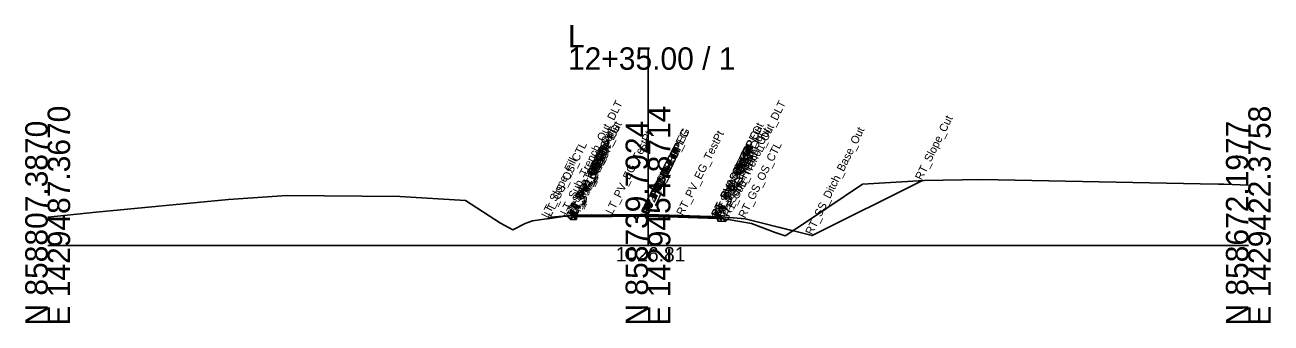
# Model space of a CAD drawing. Extents: x -26 to 2303, y -10 to 19558.
# Drawn here: x 1147.2 to 1302.8, y 990.3 to 1027.6 of the extents above; entities that cross this region are included whole.
import ezdxf

# ---------------------------------------------------------------- set-up
doc = ezdxf.new("R2010")
doc.units = 0
for name, color, linetype in [('Default', 7, 'Continuous'), ('Exist CMT Pavement', 7, 'Continuous'), ('Exist Cross Section Cell', 7, 'Continuous'), ('Exist XS Center Line Elevation Label', 7, 'Continuous'), ('Exist XS Ground Line', 7, 'Continuous'), ('Old_Level_50', 7, 'Continuous'), ('Prop CMT Pvmt Course 1', 7, 'Continuous'), ('Prop CMT Pvmt Course 1 Wedge', 7, 'Continuous'), ('Prop CMT Pvmt Course 2', 7, 'Continuous'), ('Prop CMT Pvmt Course 2 Wedge', 7, 'Continuous'), ('Prop CMT Pvmt Surface', 7, 'Continuous'), ('Prop CMT Pvmt Surface Shoulder', 7, 'Continuous'), ('Prop CMT Pvmt Wedge Surface 1', 7, 'Continuous'), ('Prop CMT Pvmt Wedge Surface 2', 7, 'Continuous'), ('Prop CMT Shld Paved Course 1', 7, 'Continuous'), ('Prop CMT Shld Paved Course 2', 7, 'Continuous'), ('Prop CMT Slope Grass', 7, 'Continuous'), ('Prop CMT Subgrade Earthwork', 7, 'Continuous'), ('Prop XS Dump Level', 7, 'Continuous')]:
    doc.layers.add(name, color=color, linetype=linetype)

msp = doc.modelspace()

# ---------------------------------------------------------------- linework, layer by layer
at = {"layer": 'Exist CMT Pavement'}
for points in [[(1225, 1003.81), (1216.08, 1003.82)], [(1216.08, 1003.82), (1220.54, 1003.82)], [(1220.54, 1003.82), (1225, 1003.81)], [(1229.37, 1003.65), (1225, 1003.81)], [(1225, 1003.81), (1233.74, 1003.47)], [(1233.74, 1003.47), (1229.37, 1003.65)]]:
    msp.add_lwpolyline(points, dxfattribs=at)
at = {"layer": 'Exist Cross Section Cell'}
for p, q in [((1225, 1000), (1225, 1024.78)), ((1150, 1000), (1225, 1000)), ((1225, 1000), (1300, 1000))]:
    msp.add_line(p, q, dxfattribs=at)
at = {"layer": 'Exist XS Ground Line'}
msp.add_lwpolyline([(1150, 1003.53), (1156.05, 1004.18), (1172.59, 1005.76), (1179.86, 1006.26), (1193.98, 1006.15), (1202.21, 1005.65), (1206.56, 1002.8), (1208.12, 1001.98), (1209.65, 1002.75), (1210.59, 1003.1), (1214.67, 1003.66), (1216.08, 1003.82), (1217.88, 1003.83), (1225.03, 1003.81), (1226.94, 1003.75), (1233.74, 1003.47), (1235.01, 1003.25), (1237.94, 1002.75), (1240.88, 1001.64), (1242.13, 1001.22), (1245.04, 1003.15), (1251.78, 1007.67), (1259.51, 1008.12), (1266.66, 1008.26), (1294, 1007.73), (1296.29, 1007.68), (1296.95, 1007.66), (1300, 1007.53)], dxfattribs=at)
at = {"layer": 'Old_Level_50'}
for p, q in [((1212.5, 1003.36), (1214.67, 1003.66)), ((1214.67, 1003.66), (1214.88, 1003.68)), ((1215.63, 1003.77), (1214.85, 1003.71)), ((1214.88, 1003.68), (1214.85, 1003.71)), ((1214.85, 1003.71), (1214.88, 1003.68)), ((1214.88, 1003.68), (1215.63, 1003.77)), ((1235.15, 1003.5), (1234.12, 1003.58)), ((1234.12, 1003.58), (1234.34, 1003.36)), ((1234.34, 1003.36), (1234.34, 1003.36)), ((1234.34, 1003.36), (1234.92, 1003.26)), ((1235.15, 1003.5), (1234.92, 1003.26)), ((1234.92, 1003.26), (1235.15, 1003.5)), ((1234.92, 1003.26), (1235.01, 1003.25))]:
    msp.add_line(p, q, dxfattribs=at)
for points in [[(1214.85, 1003.71), (1212.87, 1003.55), (1212.5, 1003.36)], [(1235.01, 1003.25), (1237.94, 1002.75), (1240.88, 1001.64), (1242.13, 1001.22), (1243.08, 1001.85)], [(1243.08, 1001.85), (1237.12, 1003.34), (1235.15, 1003.5)]]:
    msp.add_lwpolyline(points, dxfattribs=at)
at = {"layer": 'Prop CMT Pvmt Course 1'}
for points in [[(1225, 1003.89), (1215.87, 1003.79)], [(1215.87, 1003.79), (1215.87, 1003.58)], [(1215.87, 1003.58), (1216.08, 1003.58)], [(1216.08, 1003.67), (1225, 1003.76)], [(1216.08, 1003.58), (1216.08, 1003.67)], [(1225, 1003.68), (1225, 1003.89)], [(1225, 1003.89), (1234.12, 1003.58)], [(1225, 1003.68), (1225, 1003.89)], [(1225, 1003.76), (1225, 1003.68), (1225, 1003.68)], [(1233.74, 1003.47), (1225, 1003.76)], [(1225, 1003.76), (1225, 1003.68), (1225, 1003.68)], [(1233.74, 1003.38), (1233.74, 1003.47)], [(1234.12, 1003.37), (1233.74, 1003.38)], [(1234.12, 1003.58), (1234.12, 1003.37)]]:
    msp.add_lwpolyline(points, dxfattribs=at)
at = {"layer": 'Prop CMT Pvmt Course 1 Wedge'}
for points in [[(1225, 1003.76), (1216.08, 1003.67)], [(1225, 1003.76), (1233.74, 1003.47)]]:
    msp.add_lwpolyline(points, dxfattribs=at)
at = {"layer": 'Prop CMT Pvmt Course 2'}
for points in [[(1216.08, 1003.58), (1215.87, 1003.58)], [(1215.87, 1003.58), (1215.87, 1003.25)], [(1215.87, 1003.25), (1216.08, 1003.25)], [(1216.08, 1003.25), (1216.08, 1003.58)], [(1233.74, 1003.05), (1233.74, 1003.38)], [(1233.74, 1003.38), (1234.12, 1003.37)], [(1234.12, 1003.04), (1233.74, 1003.05)], [(1234.12, 1003.37), (1234.12, 1003.04)]]:
    msp.add_lwpolyline(points, dxfattribs=at)
at = {"layer": 'Prop CMT Pvmt Course 2 Wedge'}
for points in [[(1225, 1003.68), (1216.08, 1003.58)], [(1225, 1003.68), (1233.74, 1003.38)]]:
    msp.add_lwpolyline(points, dxfattribs=at)
at = {"layer": 'Prop CMT Pvmt Surface'}
for points in [[(1225, 1003.89), (1215.87, 1003.79)], [(1225, 1003.89), (1234.12, 1003.58)]]:
    msp.add_lwpolyline(points, dxfattribs=at)
at = {"layer": 'Prop CMT Pvmt Surface Shoulder'}
for points in [[(1215.87, 1003.79), (1215.87, 1003.79)], [(1234.12, 1003.58), (1234.12, 1003.58)]]:
    msp.add_lwpolyline(points, dxfattribs=at)
at = {"layer": 'Prop CMT Pvmt Wedge Surface 1'}
for points in [[(1215.87, 1003.58), (1215.87, 1003.79)], [(1216.08, 1003.58), (1215.87, 1003.58)], [(1225, 1003.76), (1216.08, 1003.67)], [(1216.08, 1003.67), (1216.08, 1003.58)], [(1225, 1003.76), (1233.74, 1003.47)], [(1233.74, 1003.47), (1233.74, 1003.38)], [(1233.74, 1003.38), (1234.12, 1003.37)], [(1234.12, 1003.37), (1234.12, 1003.58)]]:
    msp.add_lwpolyline(points, dxfattribs=at)
at = {"layer": 'Prop CMT Pvmt Wedge Surface 2'}
for points in [[(1215.87, 1003.58), (1215.87, 1003.79)], [(1225, 1003.68), (1215.87, 1003.58)], [(1225, 1003.68), (1234.12, 1003.37)], [(1234.12, 1003.37), (1234.12, 1003.58)]]:
    msp.add_lwpolyline(points, dxfattribs=at)
at = {"layer": 'Prop CMT Shld Paved Course 1'}
for points in [[(1215.87, 1003.79), (1215.66, 1003.58)], [(1215.66, 1003.58), (1215.87, 1003.58)], [(1215.87, 1003.79), (1215.87, 1003.79)], [(1215.87, 1003.58), (1215.87, 1003.79)], [(1234.12, 1003.58), (1234.12, 1003.58)], [(1234.12, 1003.58), (1234.34, 1003.36)], [(1234.12, 1003.37), (1234.12, 1003.58)], [(1234.34, 1003.36), (1234.12, 1003.37)]]:
    msp.add_lwpolyline(points, dxfattribs=at)
at = {"layer": 'Prop CMT Shld Paved Course 2'}
for points in [[(1215.66, 1003.58), (1215.32, 1003.24)], [(1215.32, 1003.24), (1215.87, 1003.25)], [(1215.87, 1003.58), (1215.66, 1003.58)], [(1215.66, 1003.58), (1215.66, 1003.58)], [(1215.87, 1003.25), (1215.87, 1003.58)], [(1234.12, 1003.37), (1234.34, 1003.36)], [(1234.12, 1003.04), (1234.12, 1003.37)], [(1234.68, 1003.02), (1234.12, 1003.04)], [(1234.34, 1003.36), (1234.34, 1003.36)], [(1234.34, 1003.36), (1234.68, 1003.02)]]:
    msp.add_lwpolyline(points, dxfattribs=at)
at = {"layer": 'Prop CMT Slope Grass'}
for points in [[(1234.12, 1003.58), (1237.12, 1003.34), (1245.49, 1001.25), (1259.2, 1008.1)], [(1215.87, 1003.79), (1212.87, 1003.55), (1212.5, 1003.36)]]:
    msp.add_lwpolyline(points, dxfattribs=at)
at = {"layer": 'Prop CMT Subgrade Earthwork'}
for points in [[(1215.32, 1003.24), (1214.85, 1003.71)], [(1215.87, 1003.25), (1215.32, 1003.24)], [(1216.08, 1003.25), (1215.87, 1003.25)], [(1216.08, 1003.25), (1216.1, 1003.82)], [(1233.74, 1003.05), (1233.72, 1003.47)], [(1233.74, 1003.05), (1234.12, 1003.04)], [(1234.12, 1003.04), (1234.68, 1003.02)], [(1234.68, 1003.02), (1235.15, 1003.5)]]:
    msp.add_lwpolyline(points, dxfattribs=at)

# ---------------------------------------------------------------- texts
at = {"layer": 'Default'}
msp.add_text('-', height=0.0001, dxfattribs=at).set_placement((1150, 1000))
at = {"layer": 'Exist Cross Section Cell'}
for s, p in [('L', (1215, 1024.78)), ('12+35.00 / 1', (1215, 1021.98))]:
    msp.add_text(s, height=2.8, dxfattribs=at).set_placement(p)
for s, p in [('E 1429487.3670', (1152.8, 990)), ('E 1429454.8714', (1227.8, 990)), ('E 1429422.3758', (1302.8, 990)), ('N 858807.3870', (1150, 990)), ('N 858739.7924', (1225, 990)), ('N 858672.1977', (1300, 990))]:
    msp.add_text(s, height=2.8, rotation=90, dxfattribs=at).set_placement(p)
at = {"layer": 'Exist XS Center Line Elevation Label'}
msp.add_text('1026.81', height=1.8, dxfattribs=at).set_placement((1220.97, 998.01))
at = {"layer": 'Prop XS Dump Level'}
for s, p in [('LT_Sub_Trench_Out_DLT', (1214.85, 1003.71)), ('RT_Sub_Trench_Out_DLT', (1235.15, 1003.5)), ('LT_PV_OEEOP_EG', (1216.08, 1003.82)), ('LT_PV_Sub_Tie_Out', (1216.1, 1003.82)), ('RT_PV_Sub_Tie_Out', (1233.72, 1003.47)), ('RT_Slope_Cut', (1259.2, 1008.1)), ('LT_Sub_Trench_Out', (1215.32, 1003.24)), ('LT_PS2_Shelf_Out', (1215.66, 1003.58)), ('LT_PV_EG_TestPt', (1220.54, 1003.82)), ('RT_PV_IEEOP_EG', (1225, 1003.81)), ('LT_PV_IEEOP_EG', (1225, 1003.81)), ('RT_PV_EG_TestPt', (1229.37, 1003.65)), ('RT_PV_OEEOP_EG', (1233.74, 1003.47)), ('RT_PS2_Shelf_Out', (1234.34, 1003.36)), ('RT_Sub_Trench_Out', (1234.68, 1003.02)), ('RT_SS_Ditch_Base_Out', (1245.49, 1001.25)), ('LT_GS_OS_CTL', (1212.87, 1003.55)), ('LT_PS2_OEOP', (1215.66, 1003.58)), ('LT_PV1_OEOT', (1215.87, 1003.79)), ('LT_PS1_OEOP', (1215.87, 1003.79)), ('LT_PV2_OEOT', (1215.87, 1003.58)), ('LT_PV1_OEEOP', (1216.08, 1003.67)), ('LT_PV2_OEEOP', (1216.08, 1003.58)), ('LT_Sub_OEEOP', (1216.08, 1003.25)), ('RT_PV1_IEEOP', (1225, 1003.76)), ('RT_PV2_IEEOP', (1225, 1003.68)), ('LT_PV1_IEEOP', (1225, 1003.76)), ('LT_PV2_IEEOP', (1225, 1003.68)), ('RT_PV1_OEEOP', (1233.74, 1003.47)), ('RT_PV2_OEEOP', (1233.74, 1003.38)), ('RT_Sub_OEEOP', (1233.74, 1003.05)), ('RT_PV1_OEOT', (1234.12, 1003.58)), ('RT_PS1_OEOP', (1234.12, 1003.58)), ('RT_PV2_OEOT', (1234.12, 1003.37)), ('RT_PS2_OEOP', (1234.34, 1003.36)), ('RT_GS_OS_CTL', (1237.12, 1003.34)), ('LT_Slope_Fill', (1212.5, 1003.36)), ('LT_Sub_OEOT', (1215.87, 1003.25)), ('RT_Sub_OEOT', (1234.12, 1003.04)), ('PV1_PGL', (1225, 1003.89)), ('PV2_PGL', (1225, 1003.68))]:
    msp.add_text(s, height=1, rotation=63.5833, dxfattribs=at).set_placement(p)

doc.saveas('drawing.dxf')
